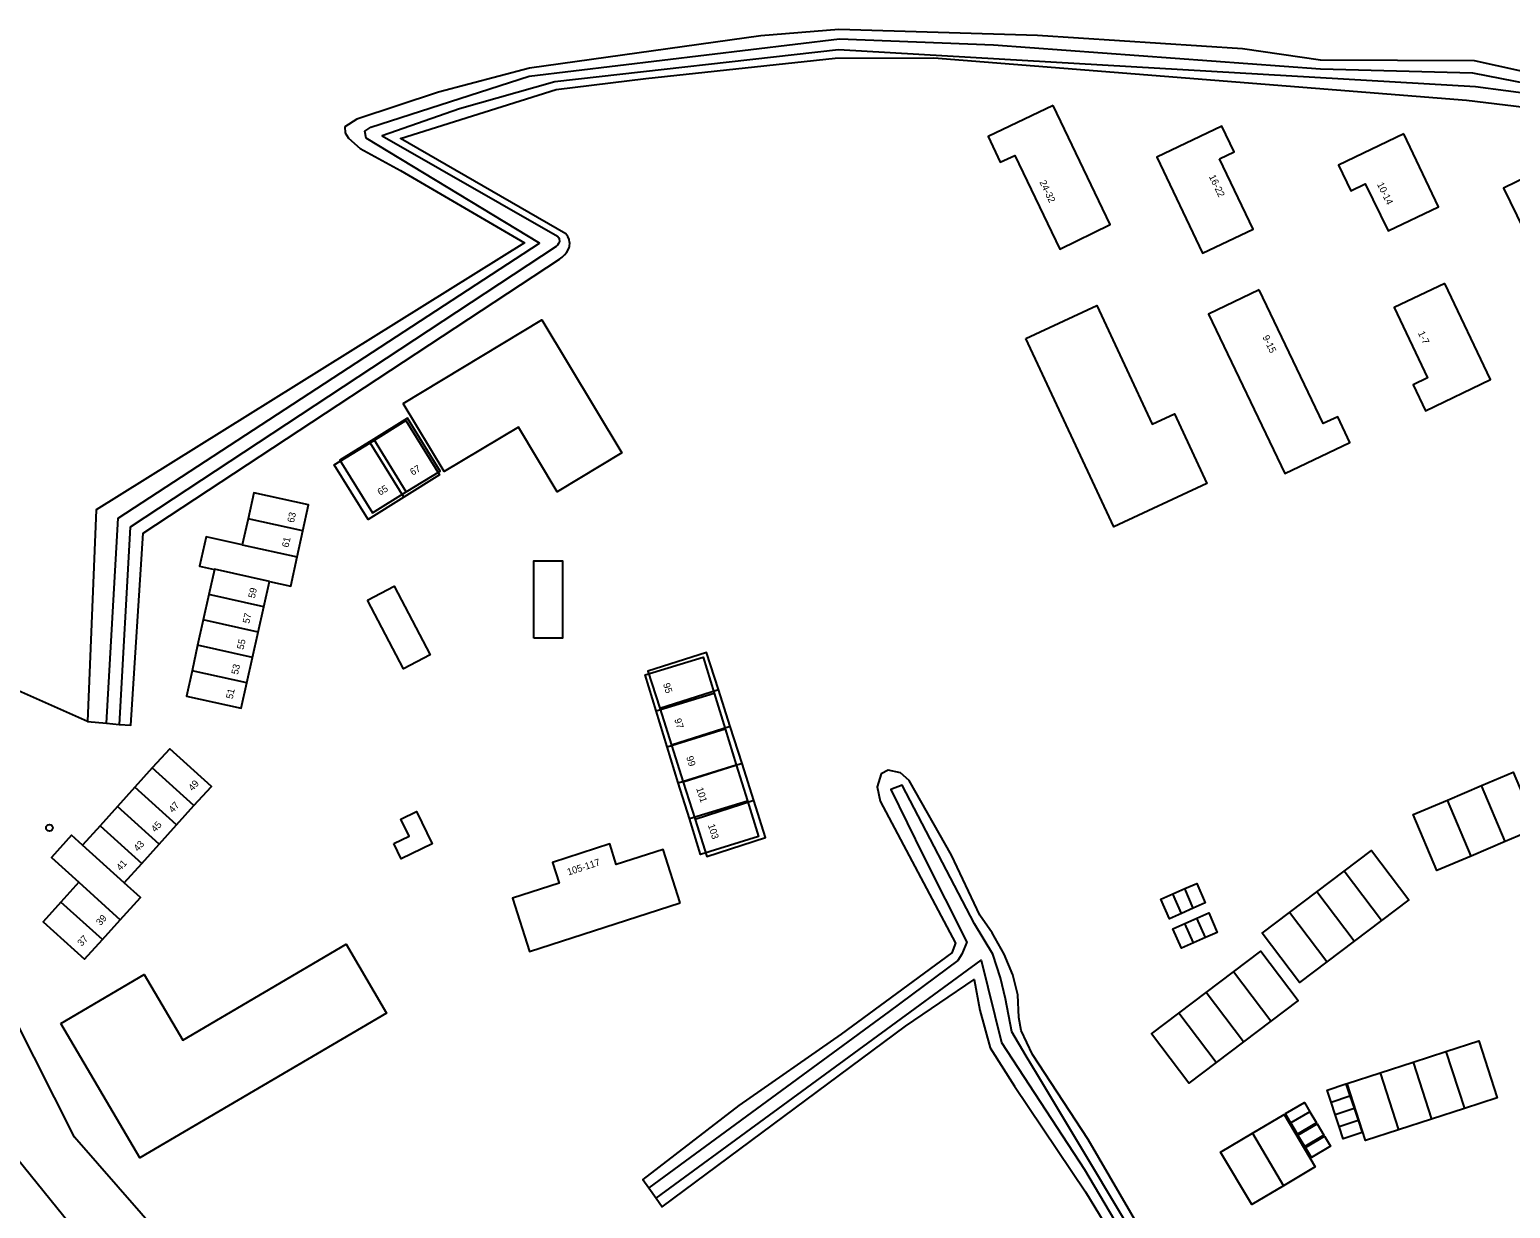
# Model space of a CAD drawing. Extents: x 159451 to 160663, y 388402 to 389723.
# Drawn here: x 159805.4 to 160018.5, y 389378.7 to 389548.3 of the extents above; entities that cross this region are included whole.
import ezdxf

# ---------------------------------------------------------------- set-up
doc = ezdxf.new("R2010")
doc.units = 0
for name, color, linetype in [('IMGEO_Boom', 7, 'Continuous'), ('IMGEO_Groenvoorziening', 7, 'Continuous'), ('IMGEO_Loofbos', 7, 'Continuous'), ('IMGEO_Pand', 7, 'Continuous'), ('IMGEO_Pand_nummerreeks', 7, 'Continuous'), ('IMGEO_Pand_vergunning_verleend', 7, 'Continuous'), ('IMGEO_Waterloop', 7, 'Continuous')]:
    doc.layers.add(name, color=color, linetype=linetype)

msp = doc.modelspace()

# ---------------------------------------------------------------- linework, layer by layer
at = {"layer": 'IMGEO_Boom'}
msp.add_circle((159808.28, 389433.41), 0.489, dxfattribs=at)
at = {"layer": 'IMGEO_Groenvoorziening'}
for points in [[(160026.85, 389540.77), (160013.37, 389543.74), (159991.18, 389543.87), (159979.98, 389545.51), (159950.46, 389547.42), (159921.89, 389548.25), (159910.67, 389547.35), (159877.37, 389542.72), (159864.26, 389539.27), (159852.5, 389535.39), (159850.81, 389534.29), (159850.85, 389533.41), (159851.33, 389532.64), (159853.01, 389531.14), (159858.8, 389527.98), (159876.64, 389517.57), (159815.03, 389479.17), (159813.75, 389448.69)], [(159818.33, 389448.3), (159819.99, 389448.16), (159821.76, 389475.8), (159881.7, 389515.21), (159882.06, 389515.52), (159882.42, 389515.86), (159882.73, 389516.23), (159883.07, 389516.85), (159883.13, 389517.08), (159883.16, 389517.57), (159883.14, 389517.69), (159883.08, 389518.04), (159882.88, 389518.48), (159882.61, 389518.89), (159858.79, 389532.6), (159881.2, 389539.62), (159894.12, 389541.21), (159921.34, 389544.14), (159935.54, 389544.19), (160012.22, 389538.08), (160041.63, 389534.55)], [(159813.75, 389448.69), (159802.55, 389453.69), (159798.18, 389441.51)], [(159813.75, 389448.69), (159816.5, 389448.46)], [(159970.06, 389367.46), (159957.78, 389388.59), (159949.76, 389400.78), (159948.12, 389404.27), (159947.78, 389406.13), (159947.66, 389409.36), (159946.9, 389412.25), (159945.66, 389415.23), (159943.96, 389418.29), (159942.16, 389420.84), (159938.08, 389429.46), (159931.99, 389440.21), (159930.75, 389441.34), (159928.96, 389441.71), (159927.97, 389441.16), (159927.38, 389439.33), (159927.82, 389437.27), (159938.68, 389416.82), (159938.12, 389415.41), (159922.23, 389403.72), (159907.5, 389393.46), (159893.69, 389382.82), (159894.54, 389381.6)], [(159895.58, 389380.11), (159896.45, 389378.88), (159931.47, 389404.89), (159941.35, 389411.59), (159942.19, 389407.16), (159943.66, 389401.77), (159947.14, 389396.23), (159957.37, 389381.03), (159966.8, 389365.6)]]:
    msp.add_lwpolyline(points, dxfattribs=at)
at = {"layer": 'IMGEO_Loofbos'}
for points in [[(159881.39, 389288.32), (159874.34, 389299.54), (159850.68, 389337.23), (159831.1, 389366.95), (159811.91, 389388.9), (159794.48, 389423.34)], [(159782.84, 389411.56), (159827.32, 389356.54), (159838.14, 389339.9), (159876.34, 389281.17)]]:
    msp.add_lwpolyline(points, dxfattribs=at)
at = {"layer": 'IMGEO_Pand'}
for points in [[(159952.74, 389537.35), (159943.35, 389532.86), (159945.12, 389529.17), (159947.23, 389530.16), (159953.67, 389516.68), (159960.91, 389520.23), (159952.74, 389537.35)], [(159976.67, 389529.64), (159978.78, 389530.65), (159977.01, 389534.35), (159967.63, 389529.9), (159974.22, 389516.08), (159981.49, 389519.54), (159976.67, 389529.64)], [(160003.18, 389533.26), (159993.78, 389528.77), (159995.55, 389525.07), (159997.61, 389526.05), (160000.92, 389519.29), (160008.18, 389522.76), (160003.18, 389533.26)], [(160026.58, 389525.29), (160028.69, 389526.32), (160026.88, 389530.02), (160017.55, 389525.44), (160024.27, 389511.69), (160031.52, 389515.23), (160026.58, 389525.29)], [(160009.07, 389511.73), (160001.8, 389508.25), (160006.61, 389498.14), (160004.51, 389497.13), (160006.29, 389493.42), (160015.67, 389497.9), (160009.07, 389511.73)], [(159982.35, 389510.81), (159975.08, 389507.33), (159986.07, 389484.37), (159995.44, 389488.85), (159993.67, 389492.55), (159991.56, 389491.57), (159982.35, 389510.81)], [(159859.64, 389481.74), (159864.51, 389484.74), (159859.82, 389492.33), (159854.95, 389489.33)], [(159854.95, 389489.33), (159850.07, 389486.32), (159854.77, 389478.73), (159859.64, 389481.74)], [(159859.64, 389481.74), (159854.95, 389489.33)], [(159844.76, 389476.14), (159845.58, 389479.88), (159837.68, 389481.63), (159836.86, 389477.88)], [(159836.86, 389477.88), (159836.03, 389474.13)], [(159844.76, 389476.14), (159836.86, 389477.88)], [(159843.92, 389472.38), (159844.76, 389476.14)], [(159836.03, 389474.13), (159830.84, 389475.29), (159829.89, 389471.07), (159832.02, 389470.6)], [(159836.03, 389474.13), (159843.92, 389472.38)], [(159839.93, 389468.87), (159843, 389468.19), (159843.92, 389472.38)], [(159832.02, 389470.6), (159831.22, 389466.97)], [(159839.93, 389468.87), (159832.02, 389470.61), (159832.02, 389470.6)], [(159831.22, 389466.97), (159830.41, 389463.32)], [(159839.12, 389465.22), (159831.22, 389466.97)], [(159839.12, 389465.22), (159839.93, 389468.87)], [(159838.31, 389461.57), (159839.12, 389465.22)], [(159830.41, 389463.32), (159829.6, 389459.67)], [(159838.31, 389461.57), (159830.41, 389463.32)], [(159837.51, 389457.92), (159838.31, 389461.57)], [(159829.6, 389459.67), (159828.8, 389456.02)], [(159837.51, 389457.92), (159829.6, 389459.67)], [(159904.55, 389453.31), (159902.86, 389458.64), (159894.39, 389455.96), (159896.1, 389450.61)], [(159836.7, 389454.27), (159837.51, 389457.92)], [(159828.8, 389456.02), (159827.99, 389452.35), (159835.89, 389450.62), (159836.7, 389454.27)], [(159836.7, 389454.27), (159828.8, 389456.02)], [(159896.1, 389450.61), (159904.55, 389453.31)], [(159906.25, 389447.98), (159904.55, 389453.31)], [(159896.1, 389450.61), (159897.79, 389445.29)], [(159906.25, 389447.98), (159897.79, 389445.29)], [(159907.95, 389442.65), (159906.25, 389447.98)], [(159829.08, 389436.6), (159831.59, 389439.38), (159825.6, 389444.8), (159823.08, 389442.02)], [(159897.79, 389445.29), (159899.49, 389439.96)], [(159823.08, 389442.02), (159820.58, 389439.25)], [(159829.08, 389436.6), (159823.08, 389442.02)], [(159907.95, 389442.65), (159899.49, 389439.96)], [(159909.65, 389437.33), (159907.95, 389442.65)], [(159820.58, 389439.25), (159818.08, 389436.47)], [(159826.58, 389433.83), (159820.58, 389439.25)], [(159899.49, 389439.96), (159901.19, 389434.63)], [(159901.19, 389434.63), (159902.88, 389429.3), (159911.35, 389432), (159909.65, 389437.33)], [(159909.65, 389437.33), (159901.19, 389434.63)], [(159818.08, 389436.47), (159815.57, 389433.7)], [(159824.07, 389431.06), (159818.08, 389436.47)], [(159826.58, 389433.83), (159829.08, 389436.6)], [(159815.57, 389433.7), (159813.06, 389430.92)], [(159815.57, 389433.7), (159821.56, 389428.28)], [(159824.07, 389431.06), (159826.58, 389433.83)], [(159813.06, 389430.92), (159811.46, 389432.36), (159808.56, 389429.15), (159812.5, 389425.58)], [(159819.06, 389425.51), (159813.06, 389430.92)], [(159821.56, 389428.28), (159824.07, 389431.06)], [(159899.04, 389422.61), (159896.59, 389430.28), (159889.86, 389428.12), (159888.91, 389431.09), (159880.66, 389428.43), (159881.62, 389425.47), (159874.9, 389423.3), (159877.36, 389415.64), (159899.04, 389422.61)], [(159819.06, 389425.51), (159821.56, 389428.28)], [(159812.5, 389425.58), (159809.94, 389422.74)], [(159812.5, 389425.58), (159818.48, 389420.18)], [(159818.48, 389420.18), (159821.39, 389423.4), (159819.06, 389425.51)], [(159809.94, 389422.74), (159807.38, 389419.91), (159813.35, 389414.51), (159815.91, 389417.35)], [(159815.91, 389417.35), (159809.94, 389422.74)], [(159815.91, 389417.35), (159818.48, 389420.18)]]:
    msp.add_lwpolyline(points, dxfattribs=at)
at = {"layer": 'IMGEO_Pand_vergunning_verleend'}
for points in [[(159948.81, 389503.83), (159959.01, 389508.58), (159966.98, 389491.47), (159970.19, 389492.97), (159974.85, 389482.95), (159961.44, 389476.7), (159948.81, 389503.83)], [(159859.2, 389494.48), (159879.13, 389506.48), (159890.64, 389487.37), (159881.35, 389481.77), (159875.76, 389491.06), (159865.11, 389484.66), (159859.2, 389494.48)], [(159854.42, 389488.82), (159859.57, 389492.01), (159864.43, 389484.18), (159859.28, 389480.98)], [(159859.28, 389480.98), (159854.13, 389477.78), (159849.27, 389485.62), (159854.42, 389488.82)], [(159859.28, 389480.98), (159854.42, 389488.82)], [(159877.97, 389460.72), (159877.97, 389471.84), (159882.1, 389471.84), (159882.1, 389460.72), (159877.97, 389460.72)], [(159854.06, 389466.18), (159857.88, 389468.19), (159863.07, 389458.32), (159859.25, 389456.31), (159854.06, 389466.18)], [(159895.6, 389450.23), (159894, 389455.4), (159902.34, 389457.97), (159903.94, 389452.8)], [(159895.6, 389450.23), (159903.94, 389452.8)], [(159903.94, 389452.8), (159905.53, 389447.64)], [(159897.19, 389445.07), (159895.6, 389450.23)], [(159897.19, 389445.07), (159905.53, 389447.64)], [(159905.53, 389447.64), (159907.12, 389442.47)], [(159898.78, 389439.9), (159897.19, 389445.07)], [(159898.78, 389439.9), (159907.12, 389442.47)], [(159907.12, 389442.47), (159908.72, 389437.3)], [(160014.38, 389439.49), (160018.94, 389441.42), (160022.34, 389433.35), (160017.78, 389431.43)], [(159900.38, 389434.73), (159898.78, 389439.9)], [(160009.46, 389437.41), (160014.38, 389439.49)], [(160017.78, 389431.43), (160014.38, 389439.49)], [(159900.38, 389434.73), (159908.72, 389437.3)], [(159908.72, 389437.3), (159910.31, 389432.14), (159901.97, 389429.56), (159900.38, 389434.73)], [(160012.86, 389429.35), (160007.93, 389427.28), (160004.53, 389435.34), (160009.46, 389437.41)], [(160012.86, 389429.35), (160009.46, 389437.41)], [(159857.86, 389431.14), (159860.05, 389432.2), (159858.85, 389434.67), (159861.11, 389435.77), (159863.36, 389431.11), (159858.92, 389428.96), (159857.86, 389431.14)], [(160017.78, 389431.43), (160012.86, 389429.35)], [(159994.6, 389427.16), (159998.52, 389430.13), (160003.89, 389423.04), (159999.97, 389420.07)], [(159990.67, 389424.19), (159994.6, 389427.16)], [(159999.97, 389420.07), (159994.6, 389427.16)], [(159969.93, 389423.9), (159971.65, 389424.66)], [(159971.65, 389424.66), (159973.38, 389425.42), (159974.61, 389422.61), (159972.89, 389421.85)], [(159972.89, 389421.85), (159971.65, 389424.66)], [(159971.17, 389421.09), (159969.45, 389420.33), (159968.21, 389423.14), (159969.93, 389423.9)], [(159971.17, 389421.09), (159969.93, 389423.9)], [(159986.75, 389421.21), (159990.67, 389424.19)], [(159996.04, 389417.09), (159990.67, 389424.19)], [(159972.89, 389421.85), (159971.17, 389421.09)], [(159971.67, 389419.65), (159973.39, 389420.41)], [(159973.39, 389420.41), (159975.11, 389421.17), (159976.35, 389418.37), (159974.63, 389417.61)], [(159974.63, 389417.61), (159973.39, 389420.41)], [(159992.12, 389414.12), (159988.19, 389411.15), (159982.82, 389418.24), (159986.75, 389421.21)], [(159992.12, 389414.12), (159986.75, 389421.21)], [(159999.97, 389420.07), (159996.04, 389417.09)], [(159972.91, 389416.85), (159971.18, 389416.08), (159969.94, 389418.89), (159971.67, 389419.65)], [(159972.91, 389416.85), (159971.67, 389419.65)], [(159809.93, 389405.25), (159821.93, 389412.29), (159827.46, 389402.87), (159850.97, 389416.67), (159856.8, 389406.76), (159821.28, 389385.91), (159809.93, 389405.25)], [(159974.63, 389417.61), (159972.91, 389416.85)], [(159996.04, 389417.09), (159992.12, 389414.12)], [(159978.66, 389412.7), (159982.59, 389415.68), (159987.96, 389408.58), (159984.04, 389405.61)], [(159974.74, 389409.73), (159978.66, 389412.7)], [(159984.04, 389405.61), (159978.66, 389412.7)], [(159970.81, 389406.75), (159974.74, 389409.73)], [(159980.11, 389402.64), (159974.74, 389409.73)], [(159976.18, 389399.66), (159972.26, 389396.69), (159966.89, 389403.78), (159970.81, 389406.75)], [(159976.18, 389399.66), (159970.81, 389406.75)], [(159984.04, 389405.61), (159980.11, 389402.64)], [(159980.11, 389402.64), (159976.18, 389399.66)], [(160004.51, 389399.7), (160009.25, 389401.23)], [(160009.25, 389401.23), (160014, 389402.76), (160016.64, 389394.56), (160011.9, 389393.03)], [(160009.25, 389401.23), (160011.9, 389393.03)], [(159999.77, 389398.17), (160004.51, 389399.7)], [(160004.51, 389399.7), (160007.15, 389391.5)], [(159992.72, 389393.92), (159992.14, 389395.68), (159994.86, 389396.58), (159995.44, 389394.83)], [(160002.41, 389389.97), (159997.66, 389388.44), (159995.02, 389396.64), (159999.77, 389398.17)], [(159999.77, 389398.17), (160002.41, 389389.97)], [(159992.72, 389393.92), (159995.44, 389394.83)], [(159995.44, 389394.83), (159996.02, 389393.08)], [(159986.93, 389390.95), (159986.14, 389392.29), (159988.89, 389393.91), (159989.68, 389392.57)], [(159989.68, 389392.57), (159986.93, 389390.95)], [(159989.68, 389392.57), (159990.64, 389390.96), (159987.89, 389389.34), (159986.93, 389390.95)], [(159993.31, 389392.17), (159992.72, 389393.92)], [(159993.31, 389392.17), (159996.02, 389393.08)], [(159996.02, 389393.08), (159996.61, 389391.33)], [(160011.9, 389393.03), (160007.15, 389391.5)], [(159981.39, 389389.47), (159985.95, 389392.17), (159990.43, 389384.63), (159985.86, 389381.92)], [(159987.95, 389389.2), (159990.7, 389390.82), (159991.67, 389389.17), (159988.92, 389387.55), (159987.95, 389389.2)], [(159993.89, 389390.42), (159993.31, 389392.17)], [(159993.89, 389390.42), (159996.61, 389391.33)], [(159996.61, 389391.33), (159997.19, 389389.57), (159994.48, 389388.67), (159993.89, 389390.42)], [(160007.15, 389391.5), (160002.41, 389389.97)], [(159985.86, 389381.92), (159981.3, 389379.22), (159976.83, 389386.76), (159981.39, 389389.47)], [(159981.39, 389389.47), (159985.86, 389381.92)], [(159989.02, 389387.44), (159991.77, 389389.06), (159992.64, 389387.59), (159989.89, 389385.97), (159989.02, 389387.44)]]:
    msp.add_lwpolyline(points, dxfattribs=at)
at = {"layer": 'IMGEO_Waterloop'}
for points in [[(159816.5, 389448.46), (159818.15, 389477.97), (159878.82, 389517.52), (159853.88, 389532.62), (159853.68, 389533.62), (159854.53, 389534.2), (159877.32, 389541.54), (159921.96, 389546.95), (159944.13, 389546.06), (159991.21, 389542.62), (160013.05, 389542.02), (160027.34, 389539.24)], [(160052.78, 389534.86), (160013.5, 389540), (159921.84, 389545.35), (159881.02, 389540.75), (159867.27, 389536.87), (159856.18, 389532.97), (159881.4, 389518.55), (159881.57, 389518.31), (159881.65, 389518.15), (159881.67, 389517.77), (159881.56, 389517.46), (159881.41, 389517.26), (159881.21, 389517.06), (159819.88, 389476.66), (159818.33, 389448.3)], [(159816.5, 389448.46), (159818.33, 389448.3)], [(159895.58, 389380.11), (159942.37, 389414.35), (159945.31, 389402.53), (159957.24, 389384.26), (159967.9, 389366.27), (159969.06, 389366.84), (159950.48, 389397.86), (159948.86, 389400.56), (159946.78, 389404.04), (159945.85, 389408.79), (159945.14, 389411.82), (159944.05, 389415.23), (159941.39, 389419.58), (159930.99, 389439.55), (159929.35, 389438.93), (159934.06, 389429.35), (159940.29, 389416.97), (159939.59, 389415.23), (159939.02, 389414.32), (159929.14, 389406.98), (159894.54, 389381.6)], [(159894.54, 389381.6), (159895.58, 389380.11)]]:
    msp.add_lwpolyline(points, dxfattribs=at)

# ---------------------------------------------------------------- texts
at = {"layer": 'IMGEO_Pand_nummerreeks'}
for s, rotation, p in [('24-32', 295.5422, (159950.73, 389526.31)), ('16-22', 295.4907, (159975.11, 389527.12)), ('10-14', 296.1095, (159999.3, 389526.01)), ('9-15', 295.5652, (159982.83, 389504.02)), ('1-7', 295.4277, (160005.19, 389504.61)), ('67', 31.6731, (159860.55, 389484.06)), ('65', 31.6731, (159855.86, 389481.17)), ('63', 77.5498, (159843.46, 389477.25)), ('61', 77.5498, (159842.68, 389473.68)), ('59', 77.5384, (159837.84, 389466.38)), ('57', 77.5384, (159837.04, 389462.74)), ('55', 77.5384, (159836.21, 389459)), ('53', 77.5384, (159835.41, 389455.4)), ('95', 287.6698, (159896.57, 389454.08)), ('51', 77.5384, (159834.64, 389451.88)), ('97', 287.6698, (159898.19, 389448.99)), ('99', 287.6698, (159899.91, 389443.57)), ('49', 47.905, (159828.89, 389438.63)), ('101', 287.6698, (159901.35, 389439.07)), ('47', 47.905, (159826.06, 389435.5)), ('45', 47.905, (159823.53, 389432.7)), ('103', 287.6698, (159903.02, 389433.81)), ('43', 47.905, (159821.02, 389429.92)), ('41', 47.905, (159818.53, 389427.16)), ('105-117', 17.8763, (159882.96, 389426.55)), ('39', 47.8649, (159815.62, 389419.26)), ('37', 47.8649, (159812.93, 389416.29))]:
    msp.add_text(s, height=1, rotation=rotation, dxfattribs=at).set_placement(p)

doc.saveas('drawing.dxf')
